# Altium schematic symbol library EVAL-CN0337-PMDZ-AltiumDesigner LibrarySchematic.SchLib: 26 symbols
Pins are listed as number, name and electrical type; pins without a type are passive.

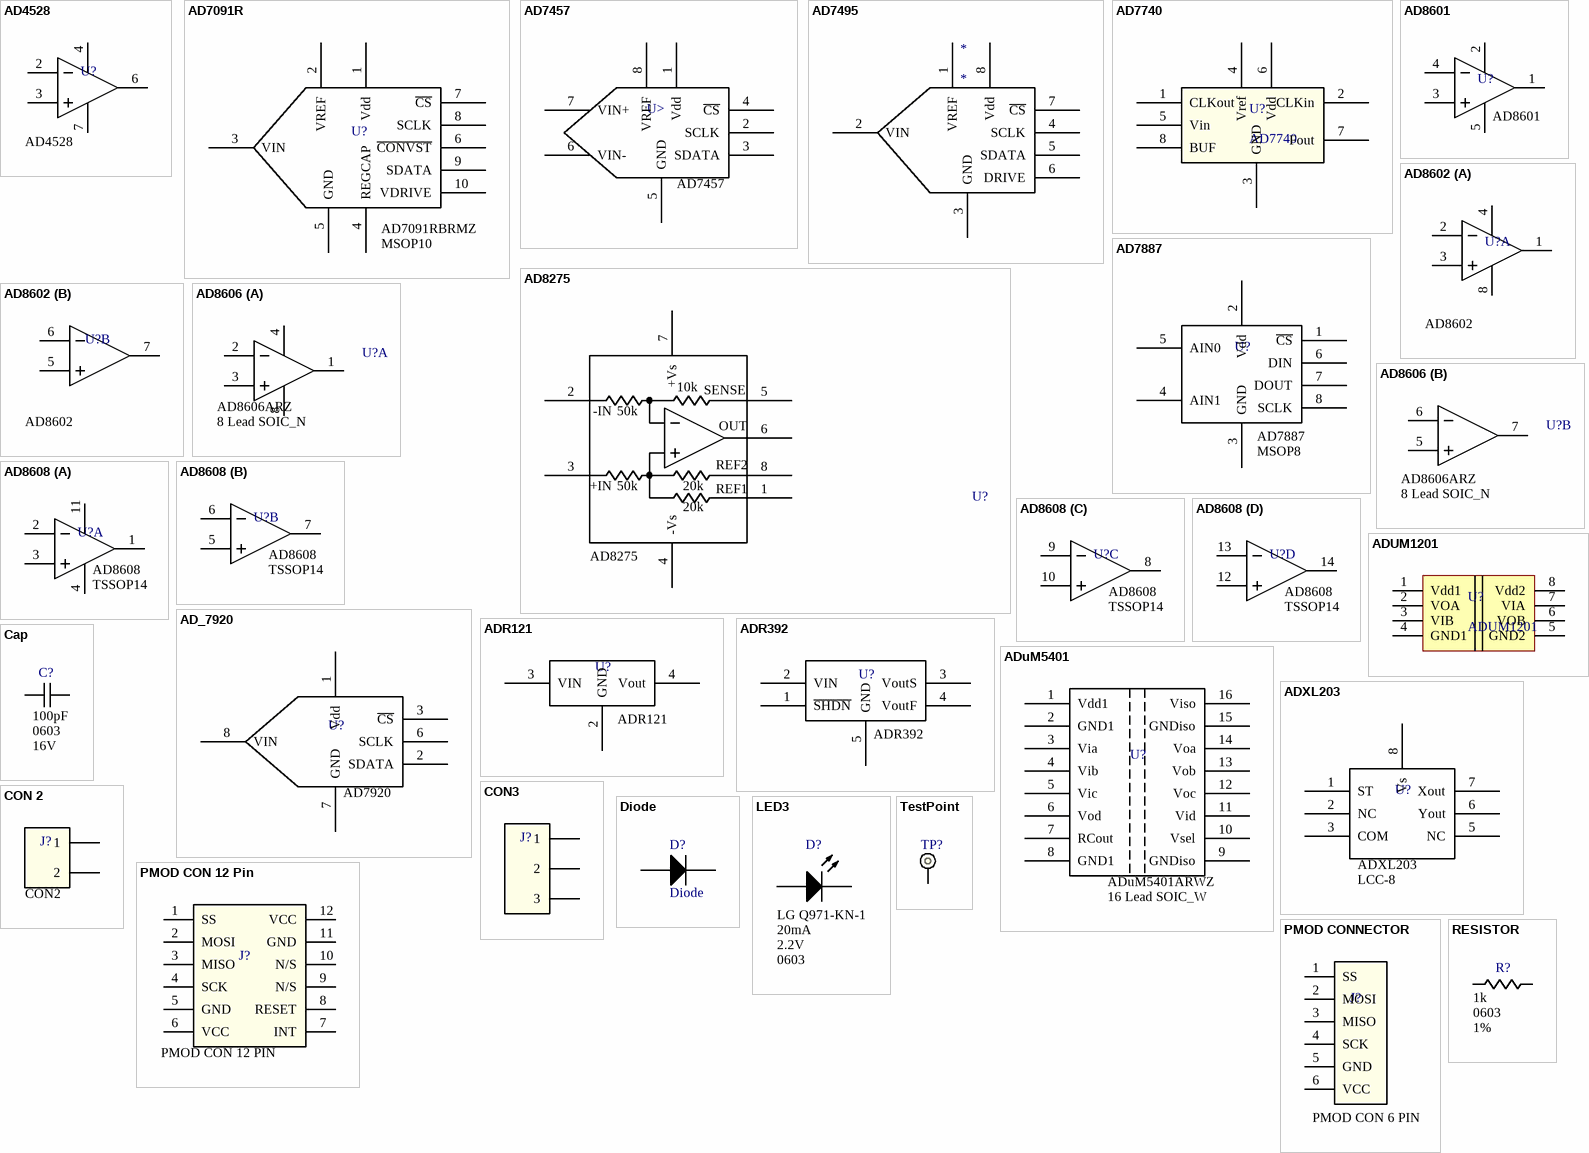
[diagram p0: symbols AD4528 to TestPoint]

## AD4528
designator U?
Operational Amplifier
pins: 2 -INA, 3 +INA, 4 V- (power), 6 OUTA, 7 V+ (power)

## AD7091R
designator U?  value AD7091RBRMZ  Footprinit: MSOP10  (hidden comment: AD7091R)
ADC
footprint MSOP10
pins: 1 Vdd, 2 VREF, 3 VIN, 4 REGCAP, 5 GND, 6 ~{CONVST}, 7 ~{CS}, 8 SCLK, 9 SDATA, 10 VDRIVE

## AD7457
designator U>
Integrated Circuit
pins: 1 Vdd, 2 SCLK, 3 SDATA, 4 ~{CS}, 5 GND, 6 VIN-, 7 VIN+, 8 VREF

## AD7495
designator *
pins: 1 VREF, 2 VIN, 3 GND, 4 SCLK, 5 SDATA, 6 DRIVE, 7 ~{CS}, 8 Vdd

## AD7740
designator U?
footprint microSO-8
pins: 1 CLKout, 2 CLKin, 3 GND, 4 Vref, 5 Vin, 6 Vdd, 7 Fout, 8 BUF

## AD7887
designator U?, comment Vlaue: AD7887  Footprint: MSOP8  (hidden comment: Analog To Digital Converter)
Integrated Ciruit
pins: 1 ~{CS}, 2 Vdd, 3 GND, 4 AIN1, 5 AIN0, 6 DIN, 7 DOUT, 8 SCLK

## AD8275
designator U?
Integrated Circuit
pins: 1 REF1, 2 -IN, 3 VIN, 4 -Vs, 5 SENSE, 6 OUT, 7 +Vs, 8 REF2

## AD8601
designator U?
Operational Amplifier
pins: 1 OUTA, 2 V- (power), 3 +INA, 4 -INA, 5 V+ (power)

## AD8602
designator U?  value AD8602
Dual Operational Amplifier
footprint SO-8
part A pins: 1 OUTA, 2 -INA, 3 +INA, 4 V+ (power), 8 V+ (power)
part B pins: 5 +INB, 6 -INB, 7 OUTB

## AD8606
designator U?  value AD8606ARZ  Footprint: 8 Lead SOIC_N
Dual Operational Amplifier; Part Number: 30-025209-01
footprint SO-8
part A pins: 1 OUTA, 2 -INA, 3 +INA, 4 V- (power), 8 V+ (power)
part B pins: 5 +INB, 6 -INB, 7 OUTB

## AD8608
designator U?  value AD8608  Footprint: TSSOP14
Operational Amplifier
part A pins: 1 OUTA, 2 -INA, 3 +INA, 4 V+ (power), 11 V- (power)
part B pins: 5 +INB, 6 -INB, 7 OUTB
part C pins: 8 OUTC, 9 -INC, 10 +INC
part D pins: 12 +IND, 13 -IND, 14 OUTD

## AD_7920
designator U?  value AD7920  (hidden comment: AD_7920)
Integrated Circuit
pins: 1 Vdd, 2 SDATA, 3 ~{CS}, 6 SCLK, 7 GND, 8 VIN

## ADR121
designator U?
Voltage Reference
pins: 2 GND, 3 VIN, 4 Vout

## ADR392
designator U?
Integrated Circuit
pins: 1 ~{SHDN}, 2 VIN, 3 VoutS, 4 VoutF, 5 GND

## ADUM1201
designator U?
footprint SO-8
pins: 1 Vdd1, 2 VOA, 3 VIB, 4 GND1, 5 GND2, 6 VOB, 7 VIA, 8 Vdd2

## ADuM5401
designator U?  value ADuM5401ARWZ  Footprint: 16 Lead SOIC_W
Quad Digital Isolator with integrated DC/DC converter; Part Number: 30-025173-01
footprint SOICW_16
pins: 1 Vdd1, 2 GND1, 3 Via, 4 Vib, 5 Vic, 6 Vod, 7 RCout, 8 GND1, 9 GNDiso, 10 Vsel, 11 Vid, 12 Voc, 13 Vob, 14 Voa, 15 GNDiso, 16 Viso

## ADXL203
designator U?, comment value ADXL203  Footprint: LCC-8  (hidden comment: TILT SENSOR)
Integrated Circuit
pins: 1 ST, 2 NC, 3 COM, 5 NC, 6 Yout, 7 Xout, 8 Vs

## Cap
designator C?  value 100pF  Footprint: 0603  Voltage: 16V
Capacitor
pins: 1, 2

## CON3
designator J?  (value not drawn)
Connector 2 Pin
footprint Phoenix_3pin_pitch2_25
pins: 1, 2, 3

## CON 2
designator J?  (value not drawn)
Input Connector
footprint Phoenix Klema pitch 2_54
pins: 1, 2

## Diode
designator D?
Default Diode
simulation model DIODE (Diode)
footprint LL34
pins: A, K

## LED3
designator D?  value LG Q971-KN-1  Drop Voltage: 2.2V  Footprint: 0603  Current: 20mA  (hidden comment: LED3)
LED; Part Number: LG Q971-KN-1-0-20-R18
pins: A, K

## PMOD CON 12 Pin
designator J?
PMOD CONNECTOR 12 PIN
pins: 1 SS, 2 MOSI, 3 MISO, 4 SCK, 5 GND, 6 VCC, 7 INT, 8 RESET, 9 N/S, 10 N/S, 11 GND, 12 VCC

## PMOD CONNECTOR
designator J?  value PMOD CON 6 PIN  (hidden comment: PMOD CONNECTOR)
CONNECTOR 6 PIN
pins: 1 SS, 2 MOSI, 3 MISO, 4 SCK, 5 GND, 6 VCC

## RESISTOR
designator R?  value 1k  Footrprint: 0603  Tolerance: 1%
Resistor
pins: 1, 2

## TestPoint
designator TP?
footprint TestPoint
pins: 1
